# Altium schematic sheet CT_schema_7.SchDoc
size 274 x 160 mm
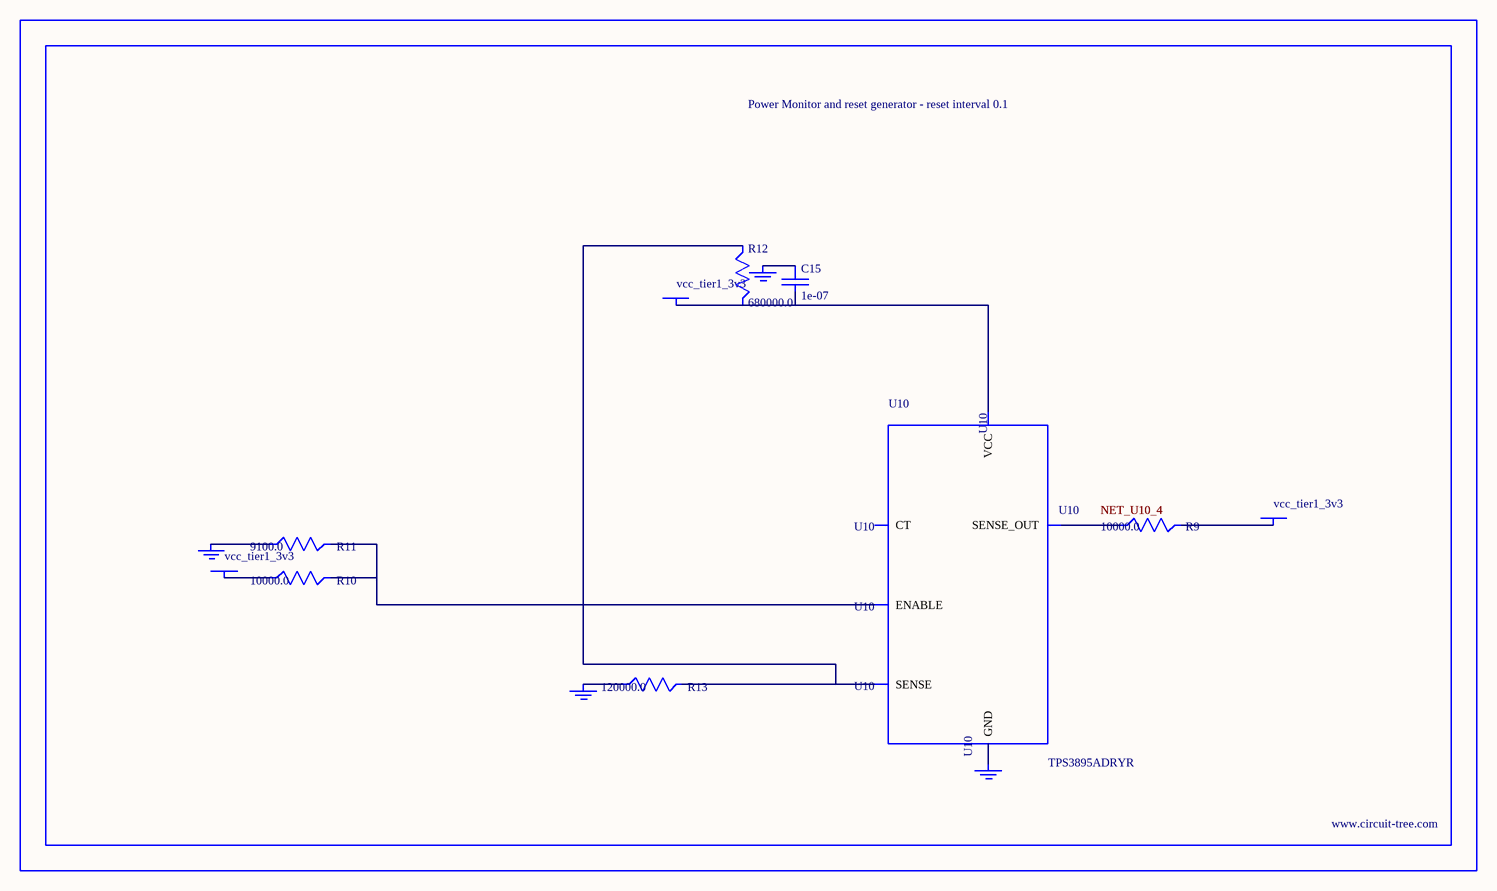
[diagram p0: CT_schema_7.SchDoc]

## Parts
BORDER6  (no value)
C15  1e-07  [C0402]
GND_INSTANCE_6_0  (no value)
GND_INSTANCE_6_1  (no value)
GND_INSTANCE_6_2  (no value)
GND_INSTANCE_6_3  (no value)
POWER_INSTANCE_6_0  vcc_tier1_3v3
POWER_INSTANCE_6_1  vcc_tier1_3v3
POWER_INSTANCE_6_2  vcc_tier1_3v3
R9  10000.0  [R0603]
R10  10000.0  [R0603]
R11  9100.0  [R0603]
R12  680000.0  [R0603]
R13  120000.0  [R0603]
U10  TPS3895ADRYR  [SON-6]

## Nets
NetC15_1: C15.1 GND_INSTANCE_6_2.0(GND)
NetC15_2: C15.2 POWER_INSTANCE_6_2.0(PWR) R12.2 U10.6(VCC)
NetGND_INSTANCE_6_0_0: GND_INSTANCE_6_0.0(GND) R11.1
NetGND_INSTANCE_6_1_0: GND_INSTANCE_6_1.0(GND) R13.1
NetGND_INSTANCE_6_3_0: GND_INSTANCE_6_3.0(GND) U10.2(GND)
NetPOWER_INSTANCE_6_0_0: POWER_INSTANCE_6_0.0(PWR) R10.1
NetPOWER_INSTANCE_6_1_0: POWER_INSTANCE_6_1.0(PWR) R9.2
NetR9_1: R9.1 U10.4(SENSE_OUT)
NetR10_2: R10.2 R11.2 U10.1(ENABLE)
NetR12_1: R12.1 R13.2 U10.3(SENSE)

Not connected (* = marked no-connect by the designer): U10 5(CT)

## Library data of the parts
BORDER6 = BORDER_PAGE6
C15 = C0402C104K3RACTU
GND_INSTANCE_6_0-GND_INSTANCE_6_3 = GND
POWER_INSTANCE_6_0-POWER_INSTANCE_6_2 = PWR
R9 R10 = RC0603JR-0710KL
R11 = RC0603JR-079K1L
R12 = RC0603JR-07680KL
R13 = RC0603JR-07120KL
